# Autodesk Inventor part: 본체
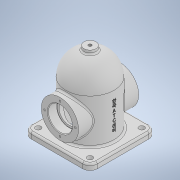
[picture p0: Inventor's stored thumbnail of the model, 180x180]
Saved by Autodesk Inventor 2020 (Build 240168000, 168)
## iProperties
Created: 2021-07
Part Number: 본체
Material: 일반
Document SubType Name: Modeling
Designer: Owner
Mass: 320.706 g
Surface Area: 800.746 cm^2
Volume: 320.706 cm^3
Density: 1 g/cm^3
Appearance: 기본값
Author: Owner
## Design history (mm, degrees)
sketch "스케치1"
  geometry: C1 r 40 at (0, 0); 1 further point
  constraints: 1 centre point, 1 coincident
  dimensions: "d0" = 80 diameter of C1
extrude "돌출1" new body sketch "스케치1" distance "d1" = 124; taper "d2" = 0 deg
fillet "모깎기1" dims "d3" = 40
feature "쉘1" dims "d4" = 8
node "작업 평면2"
sketch "스케치2"
  geometry: L1 (40, 84)-(-40, 84) reference; C1 r 31 at (0, 48); 1 further point
  constraints: 1 centre point, 1 vertical alignment
  dimensions: "d7" = 62 diameter of C1; "d8" = 48 distance of point (0, 0) C1.centre
extrude "돌출2" join sketch "스케치2" stored distance "d9" = 129; taper "d10" = 0 deg
sketch "스케치3"
  geometry: C1 r 31 at (0, 0) reference; 2 further points
  constraints: 1 coincident
hole "구멍1" sketch "스케치3" at (0, 0) diameter "d11" = 40; stored, may be unused: countersink angle "d15" = 90 deg, drill point angle "d17" = 0 deg; dims "d12" = 50, "d13" = 4, "d14" = 2, "d16" = 15
sketch "스케치4"
  geometry: C1 r 20 at (0, 0) reference; 2 further points
  constraints: 1 coincident
hole "구멍2" sketch "스케치4" at (0, 0) diameter "d18" = 33; stored, may be unused: countersink angle "d22" = 90 deg, drill point angle "d24" = 0 deg; dims "d19" = 50, "d20" = 4, "d21" = 2, "d23" = 15
sketch "스케치5"
  geometry: C1 r 31 at (0, 0) reference; 2 further points
  constraints: 1 vertical alignment
  dimensions: "d25" = 25.5 distance of C1.centre point (0, 25.5)
hole "구멍3" sketch "스케치5" at (0, 25.5) diameter "d26" = 3.242; stored, may be unused: countersink angle "d30" = 90 deg, drill point angle "d32" = 118 deg; dims "d27" = 8, "d28" = 4, "d29" = 2, "d31" = 10
node "작업 평면3"
sketch "스케치6"
  geometry: C1 r 10 at (0, 0); 1 further point
  constraints: 1 centre point, 1 coincident
  dimensions: "d37" = 20 diameter of C1
extrude "돌출3" join sketch "스케치6" stored distance "d38" = 124; taper "d39" = 0 deg
sketch "스케치7"
  geometry: C1 r 10 at (0, 0) reference; 2 further points
  constraints: 1 coincident
hole "구멍4" sketch "스케치7" at (0, 0) diameter "d40" = 5.1881; stored, may be unused: countersink angle "d44" = 90 deg, drill point angle "d46" = 118 deg; dims "d41" = 12, "d42" = 4, "d43" = 2, "d45" = 16
sketch "스케치8"
  geometry: L1 (-55, 55)-(55, 55); L2 (55, 55)-(55, -55); L3 (55, -55)-(-55, -55); L4 (-55, -55)-(-55, 55); C1 r 32 at (0, 0) reference; 3 further points
  constraints: 8 end point, 2 midpoint, 2 parallel, 1 horizontal, 1 horizontal alignment, 1 perpendicular, 1 vertical alignment
  dimensions: "d47" = 110 distance of L1.start L1.end; "d48" = 110 distance of L1.end L2.end
extrude "돌출4" join sketch "스케치8" distance "d49" = 10; taper "d50" = 0 deg
fillet "모깎기2" dims "d51" = 12
sketch "스케치9"
  geometry: A1 r 12 centre (-43, -43) between (-55, -43) and (-43, -55) reference; 2 further points
  constraints: 1 coincident
hole "구멍5" sketch "스케치9" at (-43, -43) diameter "d52" = 9; stored, may be unused: countersink angle "d56" = 90 deg, drill point angle "d58" = 0 deg; dims "d53" = 12, "d54" = 4, "d55" = 2, "d57" = 16
node "작업 평면4"
sketch "스케치10"
  geometry: L1 (0, -43)-(0, 43) reference; 3 further points
  constraints: 1 horizontal alignment, 1 midpoint, 1 other
  dimensions: "d62" = 48 distance from line of L1 point (48, 0)
feature "엠보싱1" sketch "스케치10" dims "d63" = 0.5, "d64" = 0
fillet "모깎기3" dims "d65" = 3
fillet "모깎기4" dims "d66" = 3
fillet "모깎기5" dims "d67" = 3
fillet "모깎기6" dims "d68" = 0.3
chamfer "모따기1" distance "d69" = 1; stored, may be unused: second distance "d70" = 2, angle "d71" = 45 deg
node "솔리드1"
pattern_circular "원형 패턴1" dims angle "d34" = 360 deg
mirror "미러1"
pattern_circular "원형 패턴2" dims angle "d60" = 360 deg
node "투영된 루프1"
feature "A9D066F2-1C7D-4E18-AEED-F7BC21143FA4" dims "d11" = 40, "d12" = 50, "d13" = 4, "d14" = 2, "d15" = 90 deg, "d16" = 15, "d17" = 0
other parameters: "d36" = 129
